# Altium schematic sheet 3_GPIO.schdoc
size 617 x 431 mm
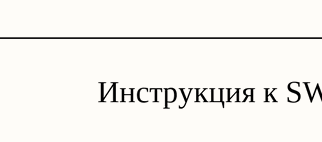
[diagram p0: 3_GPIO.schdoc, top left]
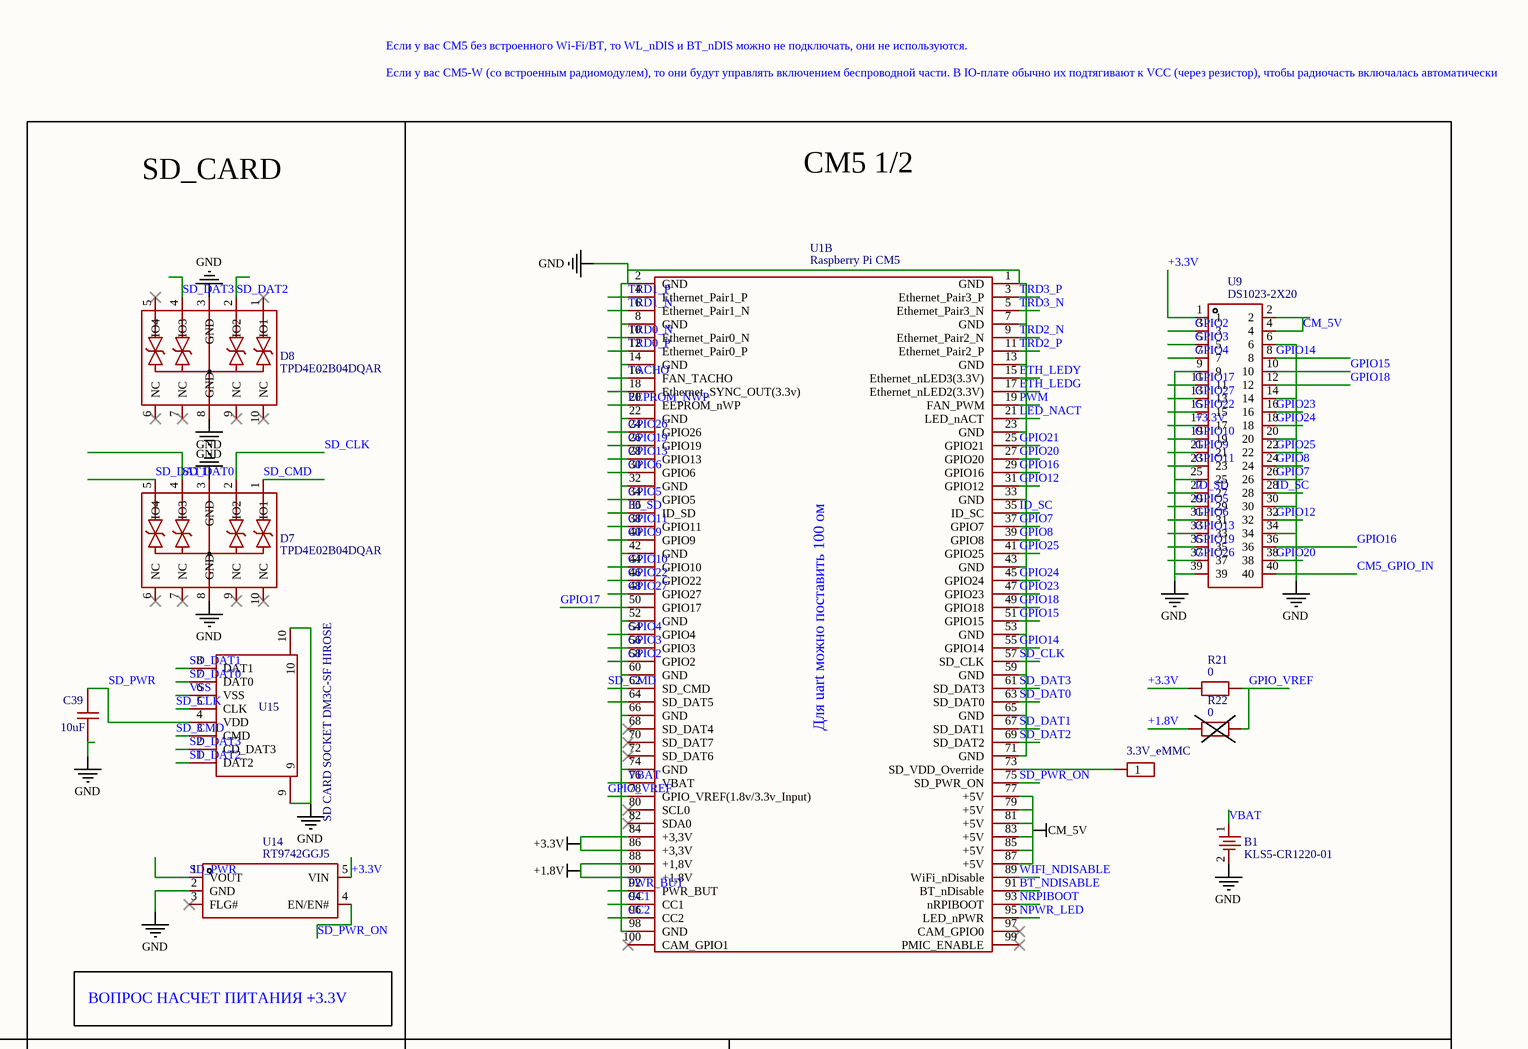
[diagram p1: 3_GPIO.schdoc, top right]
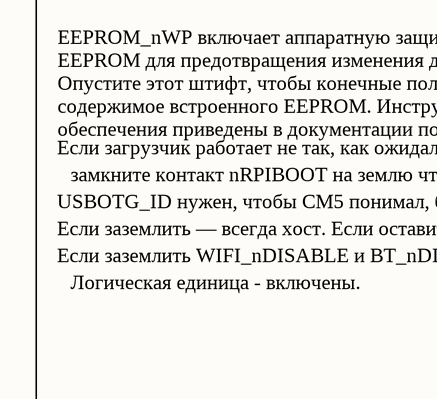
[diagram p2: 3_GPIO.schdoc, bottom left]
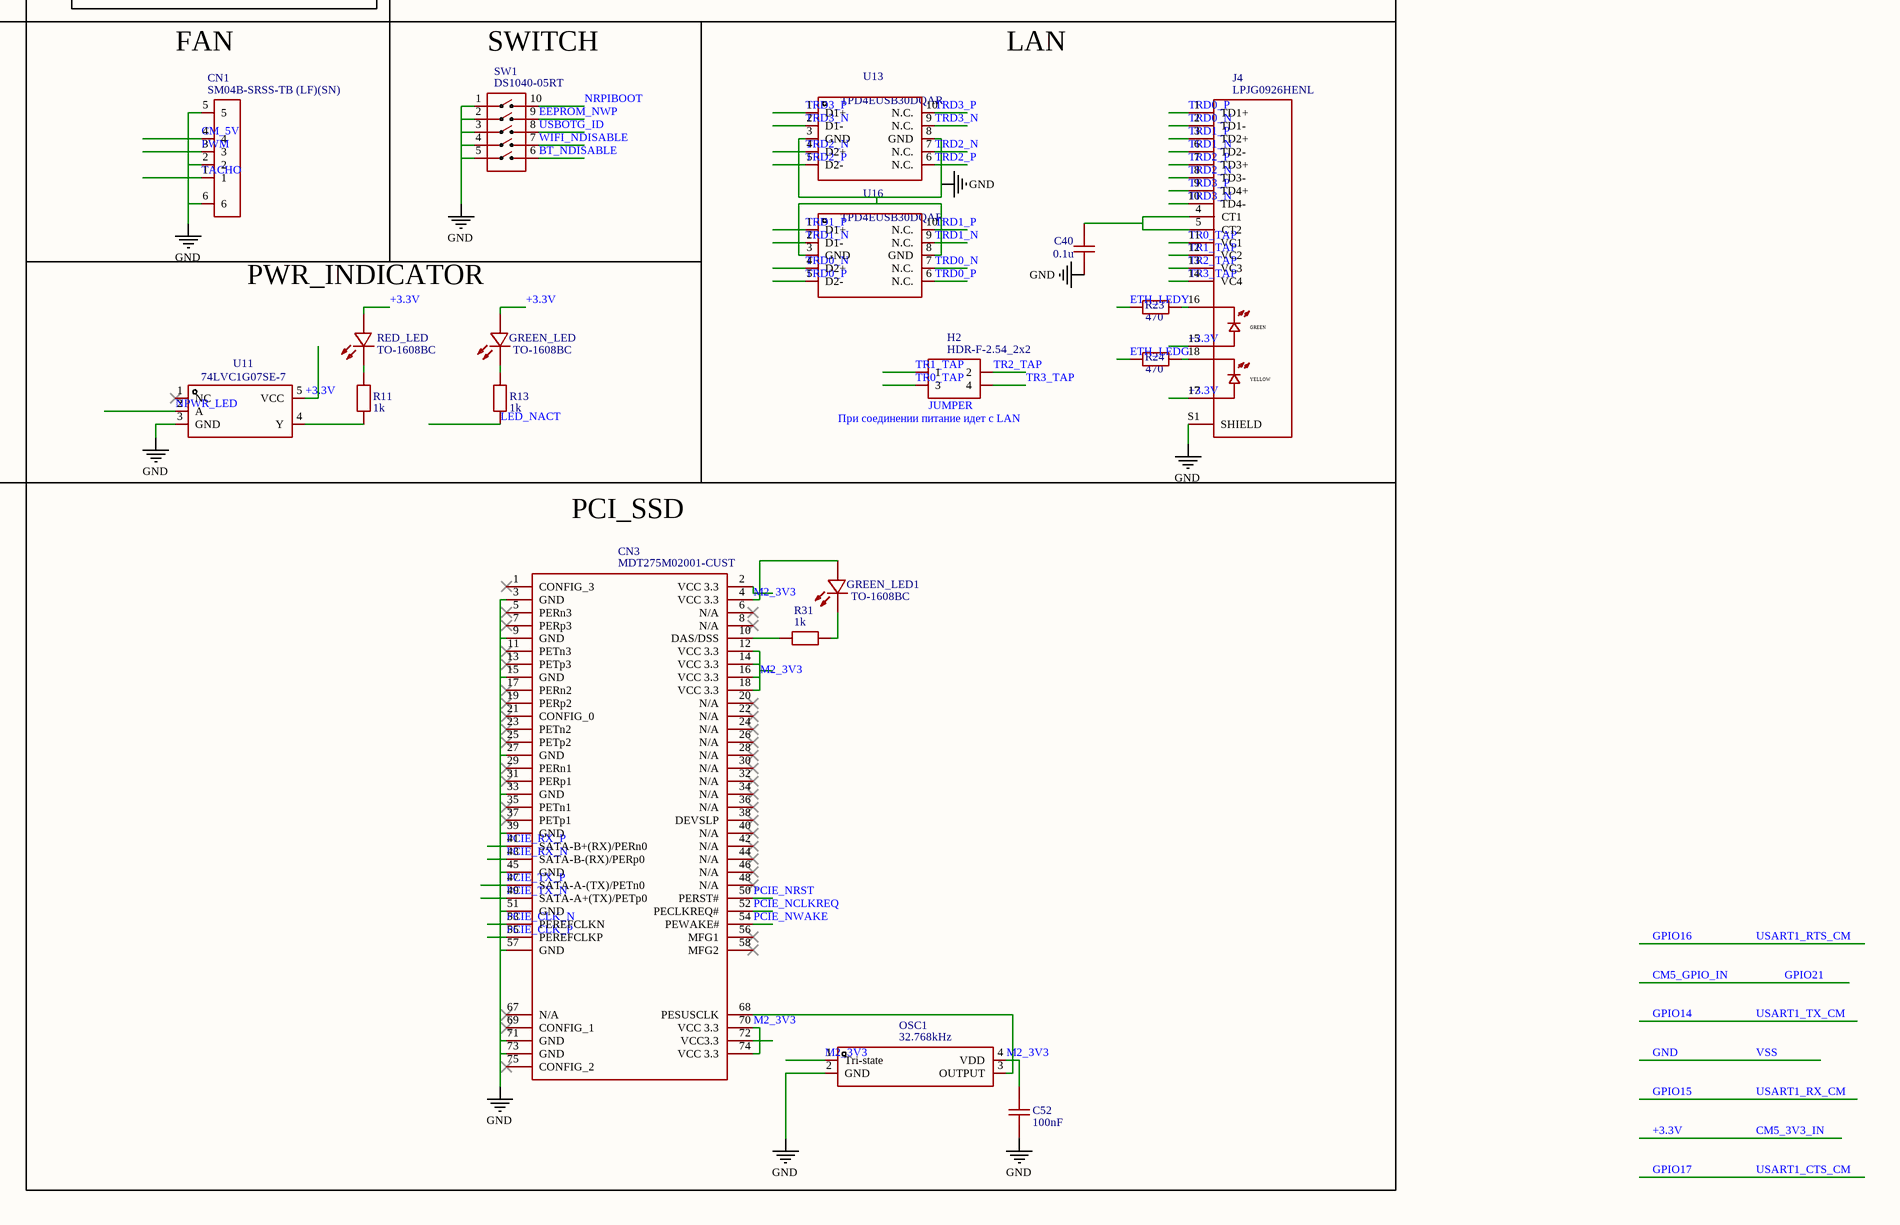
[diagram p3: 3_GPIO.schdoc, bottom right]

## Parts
B1  KLS5-CR1220-01  [L-KLS5-CR2032-23-B1]
C39  10uF  [C0603]
C40  0.1u  [C0603]
C52  100nF  [C0603]
CN1  SM04B-SRSS-TB (LF)(SN)  [CONN-SMD_4P-P1.00_SM04B-SRSS-TB-LF-SN]
CN3  MDT275M02001-CUST  [PCI-SMD_APCI0164-P001A]
D7  TPD4E02B04DQAR  [USON-10_L2.5-W1.0-P0.50-BL]
D8  TPD4E02B04DQAR  [USON-10_L2.5-W1.0-P0.50-BL]
GREEN_LED  TO-1608BC  [1608]
GREEN_LED1  TO-1608BC  [1608]
H2  HDR-F-2.54_2x2  [HDR-F-2.54_2X2]
J3  3.3V_eMMC  [HDR-M-2.54_1X1]
J4  LPJG0926HENL  [RJ45-TH_LPJG0926HENL_C22457393]
OSC1  32.768kHz  [OSC-SMD_4P-L3.2-W2.5-BL-1]
R11  1k  [R0603]
R13  1k  [R0603]
R21  0  [R0603]
R22  0  [R0603]
R23  470  [R0603]
R24  470  [R0603]
R31  1k  [R0603]
RED_LED  TO-1608BC  [SENSOR-SMD_L1.6-W0.8-XL-1608PDC]
SW1  DS1040-05RT  [SW-TH_10P-P2.54_DS1040-05RN]
U1  Raspberry Pi CM5  [CM5IO:Raspberry-Pi-5-Compute-Module]  (part B of 2)
U9  DS1023-2X20  [HDR-TH_40P-P2.00-V-F-R2-C20-S2.00]
U11  74LVC1G07SE-7  [SC-88A_L2.0-W1.3-P0.65-LS2.1-BL]
U13  TPD4EUSB30DQAR  [USON-10_L2.5-W1.0-P0.50-BL]
U14  RT9742GGJ5  [TSOT-23-5_L2.9-W1.6-P0.95-LS2.8-BR]
U15  SD CARD SOCKET DM3C-SF HIROSE  [TF-SMD_DM3CS-SF]
U16  TPD4EUSB30DQAR  [USON-10_L2.5-W1.0-P0.50-BL]

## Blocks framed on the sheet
SD_CARD: C39 D7 D8 U14 U15
CM5 1/2: B1 J3 R21 R22 U1 U9
FAN: CN1
SWITCH: SW1
LAN: C40 H2 J4 R23 R24 U13 U16
PWR_INDICATOR: GREEN_LED R11 R13 RED_LED U11
PCI_SSD: C52 CN3 GREEN_LED1 OSC1 R31

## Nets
+1.8V: R22.1 U1.88(+1,8V) U1.90(+1,8V)
+3.3V: GREEN_LED.1(A) J4.15(GA) J4.17(YA) R21.1 RED_LED.1(A) U1.84(+3,3V) U1.86(+3,3V) U9.1 U9.17 U11.5(VCC) U14.5(VIN)  [also labelled CM5_3V3_IN]
CM_5V: CN1.4 U1.77(+5V) U1.79(+5V) U1.81(+5V) U1.83(+5V) U1.85(+5V) U1.87(+5V) U9.2 U9.4
GND: B1.2 C39.1 C40.1 C52.1 CN1.2 CN1.5 CN1.6 CN3.3(GND) CN3.9(GND) CN3.15(GND) CN3.27(GND) CN3.33(GND) CN3.39(GND) CN3.45(GND) CN3.51(GND) CN3.57(GND) CN3.71(GND) CN3.73(GND) D7.3(GND) D7.8(GND) D8.3(GND) D8.8(GND) J4.S1(SHIELD) J4.S2(SHIELD) OSC1.2(GND) SW1.1 SW1.2 SW1.3 SW1.4 SW1.5 U1.1(GND) U1.2(GND) U1.7(GND) U1.8(GND) U1.13(GND) U1.14(GND) U1.22(GND) U1.23(GND) U1.32(GND) U1.33(GND) U1.42(GND) U1.43(GND) U1.52(GND) U1.53(GND) U1.59(GND) U1.60(GND) U1.65(GND) U1.66(GND) U1.71(GND) U1.74(GND) U1.98(GND) U9.6 U9.9 U9.14 U9.20 U9.25 U9.30 U9.34 U9.39 U11.3(GND) U13.3(GND) U13.8(GND) U14.2(GND) U15.6(VSS) U15.9 U15.10 U16.3(GND) U16.8(GND)  [also labelled VSS]
BT_NDISABLE: SW1.6 U1.91(BT_nDisable)
CC1: U1.94(CC1)
CC2: U1.96(CC2)
CM5_GPIO_IN: U1.25(GPIO21) U9.40  [also labelled GPIO21]
EEPROM_NWP: SW1.9 U1.20(EEPROM_nWP)
ETH_LEDG: R24.1 U1.17(Ethernet_nLED2(3.3V))
ETH_LEDY: R23.2 U1.15(Ethernet_nLED3(3.3V))
GPIO2: U1.58(GPIO2) U9.3
GPIO3: U1.56(GPIO3) U9.5
GPIO4: U1.54(GPIO4) U9.7
GPIO5: U1.34(GPIO5) U9.29
GPIO6: U1.30(GPIO6) U9.31
GPIO7: U1.37(GPIO7) U9.26
GPIO8: U1.39(GPIO8) U9.24
GPIO9: U1.40(GPIO9) U9.21
GPIO10: U1.44(GPIO10) U9.19
GPIO11: U1.38(GPIO11) U9.23
GPIO12: U1.31(GPIO12) U9.32
GPIO13: U1.28(GPIO13) U9.33
GPIO14: U1.55(GPIO14) U9.8  [also labelled USART1_TX_CM]
GPIO15: U1.51(GPIO15) U9.10  [also labelled USART1_RX_CM]
GPIO16: U1.29(GPIO16) U9.36  [also labelled USART1_RTS_CM]
GPIO17: U1.50(GPIO17) U9.11  [also labelled USART1_CTS_CM]
GPIO18: U1.49(GPIO18) U9.12
GPIO19: U1.26(GPIO19) U9.35
GPIO20: U1.27(GPIO20) U9.38
GPIO22: U1.46(GPIO22) U9.15
GPIO23: U1.47(GPIO23) U9.16
GPIO24: U1.45(GPIO24) U9.18
GPIO25: U1.41(GPIO25) U9.22
GPIO26: U1.24(GPIO26) U9.37
GPIO27: U1.48(GPIO27) U9.13
GPIO_VREF: R21.2 R22.2 U1.78(GPIO_VREF(1.8v/3.3v_Input))
ID_SC: U1.35(ID_SC) U9.28
ID_SD: U1.36(ID_SD) U9.27
LED_NACT: R13.1 U1.21(LED_nACT)
M2_3V3: C52.2 CN3.2(VCC_3.3) CN3.4(VCC_3.3) CN3.12(VCC_3.3) CN3.14(VCC_3.3) CN3.16(VCC_3.3) CN3.18(VCC_3.3) CN3.70(VCC_3.3) CN3.72(VCC3.3) CN3.74(VCC_3.3) GREEN_LED1.1(A) OSC1.1(Tri-state) OSC1.4(VDD)
NPWR_LED: U1.95(LED_nPWR) U11.2(A)
NRPIBOOT: SW1.10 U1.93(nRPIBOOT)
PCIE_CLK_N: CN3.53(PEREFCLKN)
PCIE_CLK_P: CN3.55(PEREFCLKP)
PCIE_NCLKREQ: CN3.52(PECLKREQ#)
PCIE_NRST: CN3.50(PERST#)
PCIE_NWAKE: CN3.54(PEWAKE#)
PCIE_RX_N: CN3.43(SATA-B-(RX)/PERp0)
PCIE_RX_P: CN3.41(SATA-B+(RX)/PERn0)
PCIE_TX_N: CN3.49(SATA-A+(TX)/PETp0)
PCIE_TX_P: CN3.47(SATA-A-(TX)/PETn0)
PWM: CN1.3 U1.19(FAN_PWM)
PWR_BUT: U1.92(PWR_BUT)
SD_CLK: D7.2(IO2) U1.57(SD_CLK) U15.5(CLK)
SD_CMD: D7.1(IO1) U1.62(SD_CMD) U15.3(CMD)
SD_DAT0: D7.4(IO3) U1.63(SD_DAT0) U15.7(DAT0)
SD_DAT1: D7.5(IO4) U1.67(SD_DAT1) U15.8(DAT1)
SD_DAT2: D8.2(IO2) U1.69(SD_DAT2) U15.1(DAT2)
SD_DAT3: D8.4(IO3) U1.61(SD_DAT3) U15.2(CD_DAT3)
SD_PWR: C39.2 U14.1(VOUT) U15.4(VDD)
SD_PWR_ON: U1.75(SD_PWR_ON) U14.4(EN/EN#)
TACHO: CN1.1 U1.16(FAN_TACHO)
TR0_TAP: H2.3 J4.11(VC1)
TR1_TAP: H2.1 J4.12(VC2)
TR2_TAP: H2.2 J4.13(VC3)
TR3_TAP: H2.4 J4.14(VC4)
TRD0_N: J4.2(TD1-) U1.10(Ethernet_Pair0_N) U16.4(D2+) U16.7(N.C.)
TRD0_P: J4.1(TD1+) U1.12(Ethernet_Pair0_P) U16.5(D2-) U16.6(N.C.)
TRD1_N: J4.6(TD2-) U1.6(Ethernet_Pair1_N) U16.2(D1-) U16.9(N.C.)
TRD1_P: J4.3(TD2+) U1.4(Ethernet_Pair1_P) U16.1(D1+) U16.10(N.C.)
TRD2_N: J4.8(TD3-) U1.9(Ethernet_Pair2_N) U13.4(D2+) U13.7(N.C.)
TRD2_P: J4.7(TD3+) U1.11(Ethernet_Pair2_P) U13.5(D2-) U13.6(N.C.)
TRD3_N: J4.10(TD4-) U1.5(Ethernet_Pair3_N) U13.2(D1-) U13.9(N.C.)
TRD3_P: J4.9(TD4+) U1.3(Ethernet_Pair3_P) U13.1(D1+) U13.10(N.C.)
USBOTG_ID: SW1.8
VBAT: B1.1 U1.76(VBAT)
WIFI_NDISABLE: SW1.7 U1.89(WiFi_nDisable)
NetC40_2: C40.2 J4.4(CT1) J4.5(CT2)
NetCN3_10: CN3.10(DAS/DSS) R31.2
NetCN3_68: CN3.68(PESUSCLK) OSC1.3(OUTPUT)
NetGREEN_LED1_2: GREEN_LED1.2(K) R31.1
NetGREEN_LED_2: GREEN_LED.2(K) R13.2
NetJ3_1: J3.1 U1.73(SD_VDD_Override)
NetJ4_16: J4.16(GC) R23.1
NetJ4_18: J4.18(YC) R24.2
NetR11_1: R11.1 U11.4(Y)
NetR11_2: R11.2 RED_LED.2(K)

Not connected (* = marked no-connect by the designer): CN3 1(CONFIG_3)* 5(PERn3)* 6(N/A)* 7(PERp3)* 8(N/A)* 11(PETn3)* 13(PETp3)* 17(PERn2)* 19(PERp2)* 20(N/A)* 21(CONFIG_0)* 22(N/A)* 23(PETn2)* 24(N/A)* 25(PETp2)* 26(N/A)* 28(N/A)* 29(PERn1)* 30(N/A)* 31(PERp1)* 32(N/A)* 34(N/A)* 35(PETn1)* 36(N/A)* 37(PETp1)* 38(DEVSLP)* 40(N/A)* 42(N/A)* 44(N/A)* 46(N/A)* 48(N/A)* 56(MFG1)* 58(MFG2)* 67(N/A)* 69(CONFIG_1)* 75(CONFIG_2)*; D7 6(NC)* 7(NC)* 9(NC)* 10(NC)*; D8 1(IO1)* 5(IO4)* 6(NC)* 7(NC)* 9(NC)* 10(NC)*; U1 18(Ethernet_SYNC_OUT(3.3v)) 64(SD_DAT5) 68(SD_DAT4)* 70(SD_DAT7)* 72(SD_DAT6)* 80(SCL0)* 82(SDA0)* 97(CAM_GPIO0)* 99(PMIC_ENABLE)* 100(CAM_GPIO1)*; U11 1(NC)*; U14 3(FLG#)*

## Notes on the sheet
- Если у вас CM5 без встроенного Wi-Fi/BT, то WL_nDIS и BT_nDIS можно не подключать, они не используются.
  Если у вас CM5-W (со встроенным радиомодулем), то они будут управлять включением беспроводной части. В IO-плате обычно их подтягивают к VCC (через резистор), чтобы радиочасть включалась автоматически
- (near U1) Для uart можно поставить 100 ом
- ВОПРОС НАСЧЕТ ПИТАНИЯ +3.3V
- EEPROM_nWP включает аппаратную защиту от записи в
  EEPROM для предотвращения изменения данных.
  Опустите этот штифт, чтобы конечные пользователи не могли изменять
  содержимое встроенного EEPROM. Инструкции по настройке программного
  обеспечения приведены в документации по защите EEPROM от записи.
- Инструкция к SWITCH
- Если загрузчик работает не так, как ожидалось, включите диагностические режимы:
- замкните контакт nRPIBOOT на землю чтобы принудительно включить режим загрузки по USB.
- USBOTG_ID нужен, чтобы CM5 понимал, быть ему USB-хостом или USB-устройством.
- Если заземлить — всегда хост. Если оставить открытым — будет работать как устройство (USB gadget).
- Если заземлить WIFI_nDISABLE и BT_nDISABLE - устройства вайфай и блютуз будут выключены.
- Логическая единица - включены.
- (near H2) При соединении питание идет с LAN
- (near H2) JUMPER

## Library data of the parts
B1 = KLS5-CR1220-01: Manufacturer Part: CR1220-2; Convert to PCB: yes; Contributor: LCSC
C39 = 10uF: Manufacturer: muRata(村田); Manufacturer Part: GRM188R61C106KAALD; Convert to PCB: yes; nameAlias: Value; Contributor: LCSC
C40 = 0.1u: Convert to PCB: yes; nameAlias: Value(F); Contributor: LCEDA_Lib
C52 = 100nF: Manufacturer: muRata(村田); Manufacturer Part: GRM188R72A104KA35D; Convert to PCB: yes; nameAlias: Value
CN1 = SM04B-SRSS-TB (LF)(SN): Manufacturer: JST; Convert to PCB: yes; Contributor: LCSC
CN3 = MDT275M02001-CUST: Manufacturer: Amphenol FCI; Convert to PCB: yes; Contributor: lastmins69
D7 D8 = TPD4E02B04DQAR: Manufacturer: TI(德州仪器); Convert to PCB: yes; Contributor: LCSC
GREEN_LED GREEN_LED1 RED_LED = TO-1608BC: Convert to PCB: yes; Origin Footprint: TO-1608BC-MRE; Contributor: Practical Electronic
H2 = HDR-F-2.54_2x2: Convert to PCB: yes; Contributor: LCEDA_Lib
J3 = 3.3V_eMMC: Convert to PCB: yes; Contributor: LCEDA_Lib
J4 = LPJG0926HENL: Convert to PCB: yes; Origin Footprint: LINK-PP_LPJG0926HENL; Contributor: christiansantibanez
OSC1 = 32.768kHz: Manufacturer: ABRACON; Manufacturer Part: ASEK-32.768KHZ-LRT; Convert to PCB: yes; Contributor: lcsc; nameAlias: Value
R11 R13 R31 = 1k: Convert to PCB: yes; nameAlias: Value(Ω); Contributor: LCEDA_Lib
R21 R22 = 0: Convert to PCB: yes; nameAlias: Value(Ω); Contributor: LCEDA_Lib
R23 R24 = 470: Convert to PCB: yes; nameAlias: Value(Ω); Contributor: LCEDA_Lib
SW1 = DS1040-05RT: Convert to PCB: yes; Contributor: beijinger
U1 = Raspberry Pi CM5: subpart_no: 1; Convert to PCB: yes; Origin Footprint: RASPBERRY_PI_CM5; Contributor: RobMel
U9 = DS1023-2X20: Manufacturer: XKB Connection(中国星坤); Manufacturer Part: X4621FV-2x20-C43D28; Convert to PCB: yes; Contributor: LCSC
U11 = 74LVC1G07SE-7: Manufacturer: DIODES(美台); Convert to PCB: yes; Contributor: LCSC
U13 U16 = TPD4EUSB30DQAR: Manufacturer: TI(德州仪器); Convert to PCB: yes; Contributor: LCSC
U14 = RT9742GGJ5: Manufacturer: RICHTEK(立锜); Convert to PCB: yes; Contributor: LCSC
U15 = SD CARD SOCKET DM3C-SF HIROSE: Convert to PCB: yes; Origin Footprint: SD_1:1; Contributor: Engenharia 2 R & D Mediq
